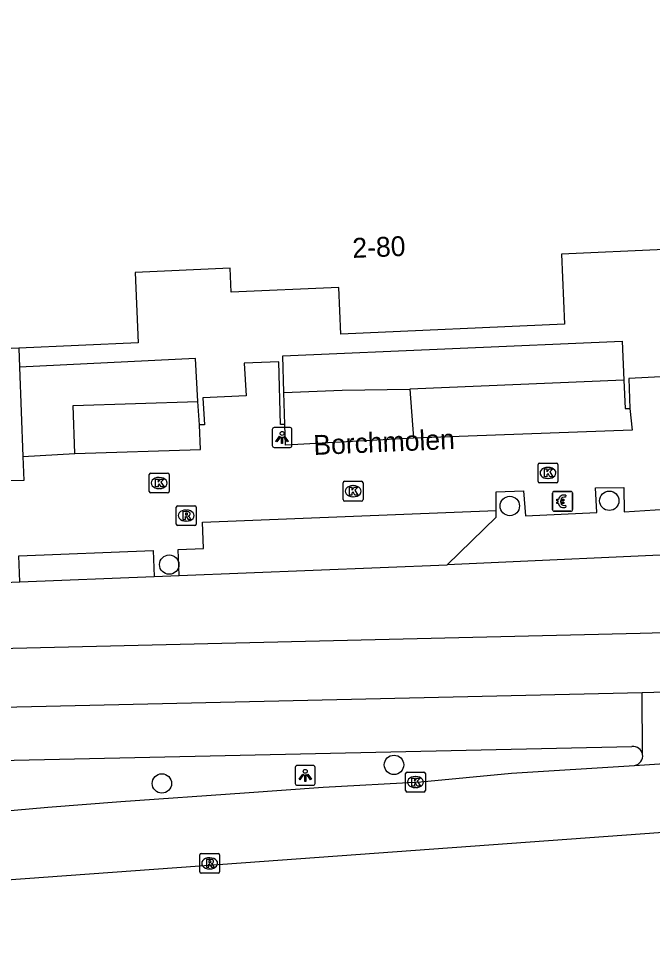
# Model space of a CAD drawing. Extents: x 161243 to 161752, y 384138 to 384885.
# Drawn here: x 161303.77 to 161335.74, y 384140.88 to 384187.42 of the extents above; entities that cross this region are included whole.
import ezdxf

# ---------------------------------------------------------------- set-up
doc = ezdxf.new("R2010")
doc.units = 0
for name, color, linetype in [('IMGEO_Betaalautomaat', 7, 'Continuous'), ('IMGEO_Boom', 7, 'Continuous'), ('IMGEO_Fietspad_gesloten', 7, 'Continuous'), ('IMGEO_Groenvoorziening', 7, 'Continuous'), ('IMGEO_Kolk', 7, 'Continuous'), ('IMGEO_Lichtpunt', 7, 'Continuous'), ('IMGEO_Openbare_ruimte_label', 7, 'Continuous'), ('IMGEO_Pand', 7, 'Continuous'), ('IMGEO_Pand_nummerreeks', 7, 'Continuous'), ('IMGEO_Parkeervlak_open', 7, 'Continuous'), ('IMGEO_Rijbaan_lokaal_gesloten', 7, 'Continuous'), ('IMGEO_Rijbaan_lokaal_open', 7, 'Continuous'), ('IMGEO_Rioolput', 7, 'Continuous'), ('IMGEO_Voetpad_open', 7, 'Continuous')]:
    doc.layers.add(name, color=color, linetype=linetype)

msp = doc.modelspace()

# ---------------------------------------------------------------- linework, layer by layer
at = {"layer": 'IMGEO_Betaalautomaat'}
for p, q in [((161330.699, 384162.651), (161330.699, 384163.492)), ((161330.699, 384163.492), (161330.699, 384162.651)), ((161330.774, 384163.575), (161331.615, 384163.575)), ((161331.615, 384163.575), (161330.774, 384163.575)), ((161331.698, 384163.501), (161331.698, 384162.66)), ((161331.698, 384162.66), (161331.698, 384163.501)), ((161330.982, 384163.039), (161330.982, 384163.107)), ((161331.103, 384163.107), (161331.103, 384163.039)), ((161331.361, 384163.38), (161331.344, 384163.28)), ((161331.624, 384162.576), (161330.783, 384162.576)), ((161330.783, 384162.576), (161331.624, 384162.576)), ((161331.348, 384162.874), (161331.37, 384162.787))]:
    msp.add_line(p, q, dxfattribs=at)
for points in [[(161330.982, 384163.107), (161330.913, 384163.107), (161330.913, 384163.176), (161330.992, 384163.176)], [(161330.987, 384162.97), (161330.913, 384162.97), (161330.913, 384163.039), (161330.982, 384163.039)], [(161331.114, 384163.176), (161331.261, 384163.176), (161331.261, 384163.107), (161331.103, 384163.107)], [(161331.103, 384163.039), (161331.261, 384163.039), (161331.261, 384162.97), (161331.117, 384162.97)]]:
    msp.add_lwpolyline(points, dxfattribs=at)
for centre, radius, start, end in [((161330.777, 384163.498), 0.0779, 92.4484, 184.2845), ((161330.777, 384163.498), 0.0779, 92.4484, 184.2845), ((161331.621, 384163.498), 0.0779, 2.4484, 94.2845), ((161331.621, 384163.498), 0.0779, 2.4484, 94.2845), ((161331.248, 384163.025), 0.267, 191.8096, 297.0389), ((161331.275, 384163.1), 0.293, 73.014, 165.0139), ((161331.281, 384163.113), 0.179, 69.3236, 159.5683), ((161331.281, 384163.04), 0.179, 202.7625, 291.8693), ((161330.777, 384162.654), 0.0779, 182.4484, 274.2845), ((161330.777, 384162.654), 0.0779, 182.4484, 274.2845), ((161331.621, 384162.654), 0.0779, 272.4484, 4.2845), ((161331.621, 384162.654), 0.0779, 272.4484, 4.2845)]:
    msp.add_arc(centre, radius, start, end, dxfattribs=at)
at = {"layer": 'IMGEO_Boom'}
for centre in [(161333.558, 384163.104), (161328.543, 384162.84), (161311.37, 384159.885), (161322.704, 384149.79), (161310.999, 384148.852)]:
    msp.add_circle(centre, 0.489, dxfattribs=at)
at = {"layer": 'IMGEO_Fietspad_gesloten'}
for points in [[(161335.217, 384153.424), (161294.886, 384152.501), (161264.254, 384151.917)], [(161262.525, 384149.114), (161334.701, 384150.711)]]:
    msp.add_lwpolyline(points, dxfattribs=at)
msp.add_arc((161334.763, 384150.231), 0.484, 9.9926, 97.3984, dxfattribs=at)
at = {"layer": 'IMGEO_Groenvoorziening'}
for points in [[(161317.154, 384168.56), (161317.096, 384170.413), (161334.208, 384171.151), (161334.294, 384169.18)], [(161312.811, 384168.108), (161312.699, 384170.282), (161303.821, 384169.831)], [(161334.294, 384169.18), (161323.501, 384168.735)], [(161334.294, 384169.18), (161334.357, 384167.748), (161334.6, 384167.762)], [(161352.045, 384161.086), (161325.389, 384159.875)]]:
    msp.add_lwpolyline(points, dxfattribs=at)
at = {"layer": 'IMGEO_Kolk'}
for p, q in [((161329.965, 384164.081), (161329.965, 384164.933)), ((161330.04, 384165.007), (161330.892, 384165.007)), ((161330.966, 384164.933), (161330.966, 384164.081)), ((161310.362, 384163.572), (161310.362, 384164.424)), ((161310.437, 384164.498), (161311.289, 384164.498)), ((161311.363, 384164.424), (161311.363, 384163.572)), ((161330.453, 384164.787), (161330.478, 384164.787)), ((161310.85, 384164.278), (161310.875, 384164.278)), ((161320.14, 384163.16), (161320.14, 384164.012)), ((161320.215, 384164.086), (161321.067, 384164.086)), ((161321.141, 384164.012), (161321.141, 384163.16)), ((161330.892, 384164.007), (161330.04, 384164.007)), ((161330.476, 384164.227), (161330.451, 384164.227)), ((161311.289, 384163.498), (161310.437, 384163.498)), ((161310.873, 384163.718), (161310.848, 384163.718)), ((161320.628, 384163.866), (161320.653, 384163.866)), ((161321.067, 384163.086), (161320.215, 384163.086)), ((161320.651, 384163.306), (161320.626, 384163.306)), ((161323.286, 384148.494), (161323.286, 384149.346)), ((161323.361, 384149.42), (161324.213, 384149.42)), ((161323.774, 384149.2), (161323.799, 384149.2)), ((161324.287, 384149.346), (161324.287, 384148.494)), ((161323.797, 384148.64), (161323.772, 384148.64)), ((161324.213, 384148.42), (161323.361, 384148.42))]:
    msp.add_line(p, q, dxfattribs=at)
for points in [[(161329.965, 384164.081), (161329.965, 384164.933)], [(161330.04, 384165.007), (161330.892, 384165.007)], [(161330.966, 384164.933), (161330.966, 384164.081)], [(161310.362, 384163.572), (161310.362, 384164.424)], [(161310.437, 384164.498), (161311.289, 384164.498)], [(161311.363, 384164.424), (161311.363, 384163.572)], [(161330.286, 384164.707), (161330.409, 384164.707), (161330.409, 384164.556), (161330.539, 384164.707), (161330.703, 384164.707), (161330.557, 384164.556), (161330.71, 384164.307), (161330.558, 384164.307), (161330.473, 384164.471), (161330.409, 384164.404), (161330.409, 384164.307), (161330.286, 384164.307), (161330.286, 384164.707)], [(161310.683, 384164.198), (161310.806, 384164.198), (161310.806, 384164.047), (161310.936, 384164.198), (161311.1, 384164.198), (161310.954, 384164.047), (161311.107, 384163.798), (161310.955, 384163.798), (161310.87, 384163.962), (161310.806, 384163.895), (161310.806, 384163.798), (161310.683, 384163.798), (161310.683, 384164.198)], [(161320.14, 384163.16), (161320.14, 384164.012)], [(161320.215, 384164.086), (161321.067, 384164.086)], [(161321.141, 384164.012), (161321.141, 384163.16)], [(161330.892, 384164.007), (161330.04, 384164.007)], [(161311.289, 384163.498), (161310.437, 384163.498)], [(161320.461, 384163.786), (161320.584, 384163.786), (161320.584, 384163.635), (161320.714, 384163.786), (161320.878, 384163.786), (161320.732, 384163.635), (161320.885, 384163.386), (161320.733, 384163.386), (161320.648, 384163.55), (161320.584, 384163.483), (161320.584, 384163.386), (161320.461, 384163.386), (161320.461, 384163.786)], [(161321.067, 384163.086), (161320.215, 384163.086)], [(161323.286, 384148.494), (161323.286, 384149.346)], [(161323.361, 384149.42), (161324.213, 384149.42)], [(161323.607, 384149.12), (161323.73, 384149.12), (161323.73, 384148.969), (161323.86, 384149.12), (161324.024, 384149.12), (161323.878, 384148.969), (161324.031, 384148.72), (161323.879, 384148.72), (161323.794, 384148.884), (161323.73, 384148.817), (161323.73, 384148.72), (161323.607, 384148.72), (161323.607, 384149.12)], [(161324.287, 384149.346), (161324.287, 384148.494)], [(161324.213, 384148.42), (161323.361, 384148.42)]]:
    msp.add_lwpolyline(points, dxfattribs=at)
for centre, start, end in [((161330.042, 384164.931), 91.552, 178.448), ((161330.042, 384164.931), 91.552, 178.448), ((161330.89, 384164.931), 1.552, 88.448), ((161330.89, 384164.931), 1.552, 88.448), ((161310.439, 384164.422), 91.552, 178.448), ((161310.439, 384164.422), 91.552, 178.448), ((161311.287, 384164.422), 1.552, 88.448), ((161311.287, 384164.422), 1.552, 88.448), ((161320.217, 384164.01), 91.552, 178.448), ((161320.217, 384164.01), 91.552, 178.448), ((161321.065, 384164.01), 1.552, 88.448), ((161321.065, 384164.01), 1.552, 88.448), ((161330.042, 384164.083), 181.552, 268.448), ((161330.042, 384164.083), 181.552, 268.448), ((161330.89, 384164.083), 271.552, 358.448), ((161330.89, 384164.083), 271.552, 358.448), ((161310.439, 384163.574), 181.552, 268.448), ((161310.439, 384163.574), 181.552, 268.448), ((161311.287, 384163.574), 271.552, 358.448), ((161311.287, 384163.574), 271.552, 358.448), ((161320.217, 384163.162), 181.552, 268.448), ((161320.217, 384163.162), 181.552, 268.448), ((161321.065, 384163.162), 271.552, 358.448), ((161321.065, 384163.162), 271.552, 358.448), ((161323.363, 384149.344), 91.552, 178.448), ((161323.363, 384149.344), 91.552, 178.448), ((161324.211, 384149.344), 1.552, 88.448), ((161324.211, 384149.344), 1.552, 88.448), ((161323.363, 384148.496), 181.552, 268.448), ((161323.363, 384148.496), 181.552, 268.448), ((161324.211, 384148.496), 271.552, 358.448), ((161324.211, 384148.496), 271.552, 358.448)]:
    msp.add_arc(centre, 0.0765, start, end, dxfattribs=at)
for centre, major_axis, ratio, start_param, end_param in [((161330.452, 384164.507), (-0.387, 0.002), 0.722429, 4.712389, 7.853982), ((161330.477, 384164.507), (-0.39, 0.002), 0.717154, 1.570796, 4.712389), ((161310.849, 384163.998), (-0.387, 0.002), 0.722429, 4.712389, 7.853982), ((161310.874, 384163.998), (-0.39, 0.002), 0.717154, 1.570796, 4.712389), ((161320.627, 384163.586), (-0.387, 0.002), 0.722429, 4.712389, 7.853982), ((161320.652, 384163.586), (-0.39, 0.002), 0.717154, 1.570796, 4.712389), ((161323.773, 384148.92), (-0.387, 0.002), 0.722429, 4.712389, 7.853982), ((161323.798, 384148.92), (-0.39, 0.002), 0.717154, 1.570796, 4.712389)]:
    msp.add_ellipse(centre, major_axis=major_axis, ratio=ratio, start_param=start_param, end_param=end_param, dxfattribs=at)
at = {"layer": 'IMGEO_Lichtpunt'}
for p, q in [((161316.562, 384166.698), (161316.562, 384165.891)), ((161316.562, 384166.698), (161316.562, 384165.891)), ((161317.464, 384166.793), (161316.656, 384166.793)), ((161317.464, 384166.793), (161316.656, 384166.793)), ((161317.558, 384165.891), (161317.558, 384166.698)), ((161317.558, 384165.891), (161317.558, 384166.698)), ((161316.656, 384165.797), (161317.464, 384165.797)), ((161316.656, 384165.797), (161317.464, 384165.797)), ((161317.726, 384149.664), (161317.726, 384148.857)), ((161317.726, 384149.664), (161317.726, 384148.857)), ((161318.628, 384149.759), (161317.82, 384149.759)), ((161318.628, 384149.759), (161317.82, 384149.759)), ((161318.722, 384148.857), (161318.722, 384149.664)), ((161318.722, 384148.857), (161318.722, 384149.664)), ((161317.82, 384148.763), (161318.628, 384148.763)), ((161317.82, 384148.763), (161318.628, 384148.763))]:
    msp.add_line(p, q, dxfattribs=at)
for points in [[(161316.936, 384166.362), (161316.975, 384166.334), (161316.787, 384166.072), (161316.749, 384166.099), (161316.936, 384166.362)], [(161317.038, 384166.314), (161317.085, 384166.314), (161317.085, 384165.992), (161317.038, 384165.992), (161317.038, 384166.314)], [(161317.148, 384166.334), (161317.186, 384166.361), (161317.373, 384166.099), (161317.334, 384166.071), (161317.148, 384166.334)], [(161318.1, 384149.328), (161318.139, 384149.3), (161317.951, 384149.038), (161317.913, 384149.065), (161318.1, 384149.328)], [(161318.202, 384149.28), (161318.249, 384149.28), (161318.249, 384148.958), (161318.202, 384148.958), (161318.202, 384149.28)], [(161318.312, 384149.3), (161318.35, 384149.327), (161318.537, 384149.065), (161318.498, 384149.037), (161318.312, 384149.3)]]:
    msp.add_lwpolyline(points, dxfattribs=at)
for centre in [(161317.061, 384166.496), (161318.225, 384149.462)]:
    msp.add_circle(centre, 0.0994, dxfattribs=at)
for centre, start, end in [((161316.656, 384166.698), 90, 180), ((161316.656, 384166.698), 90, 180), ((161317.464, 384166.698), 0, 90), ((161317.464, 384166.698), 0, 90), ((161316.656, 384165.891), 180, 270), ((161316.656, 384165.891), 180, 270), ((161317.464, 384165.891), 270, 0), ((161317.464, 384165.891), 270, 360), ((161317.82, 384149.664), 90, 180), ((161317.82, 384149.664), 90, 180), ((161318.628, 384149.664), 0, 90), ((161318.628, 384149.664), 0, 90), ((161317.82, 384148.857), 180, 270), ((161317.82, 384148.857), 180, 270), ((161318.628, 384148.857), 270, 0), ((161318.628, 384148.857), 270, 360)]:
    msp.add_arc(centre, 0.0946, start, end, dxfattribs=at)
at = {"layer": 'IMGEO_Pand'}
for points in [[(161354.21, 384187.419), (161352.267, 384187.333), (161352.85, 384174.043), (161347.371, 384173.803), (161347.422, 384172.637), (161341.583, 384172.381), (161341.478, 384174.793), (161336.389, 384174.569), (161336.336, 384175.763), (161331.14, 384175.535), (161331.295, 384172.004), (161320.023, 384171.509), (161319.92, 384173.854), (161314.498, 384173.616), (161314.445, 384174.825), (161309.65, 384174.615), (161309.805, 384171.068), (161303.785, 384170.804)], [(161303.785, 384170.804), (161301.481, 384170.703)]]:
    msp.add_lwpolyline(points, dxfattribs=at)
at = {"layer": 'IMGEO_Parkeervlak_open'}
for points in [[(161317.154, 384168.56), (161320.082, 384168.674), (161323.501, 384168.735)], [(161317.204, 384166.951), (161317.154, 384168.56)], [(161323.501, 384168.735), (161323.686, 384166.264)], [(161306.603, 384165.479), (161306.523, 384167.901), (161312.811, 384168.108)], [(161312.894, 384166.937), (161312.811, 384168.108)], [(161325.389, 384159.875), (161327.853, 384162.271), (161327.854, 384162.612)], [(161311.865, 384159.331), (161325.389, 384159.875)], [(161303.835, 384159.009), (161310.616, 384159.281)]]:
    msp.add_lwpolyline(points, dxfattribs=at)
at = {"layer": 'IMGEO_Rijbaan_lokaal_gesloten'}
for points in [[(161371.088, 384154.255), (161366.206, 384154.17), (161362.935, 384154.07), (161357.372, 384153.915), (161350.419, 384153.771), (161345.195, 384153.611), (161343.385, 384153.579), (161338.774, 384153.519), (161335.217, 384153.424)], [(161335.24, 384150.315), (161335.217, 384153.424)], [(161334.833, 384149.765), (161370.321, 384152.118), (161401.777, 384153.037)], [(161403.252, 384150.18), (161392.155, 384149.886), (161376.721, 384149.233), (161369.626, 384148.76), (161361.232, 384148.2), (161341.125, 384146.731), (161314.989, 384144.831), (161288.79, 384142.926), (161262, 384140.882)], [(161262.281, 384144.461), (161263.157, 384144.513), (161268.286, 384144.952), (161279.348, 384145.71), (161300.005, 384147.288), (161301.599, 384147.407), (161303.55, 384147.498), (161305.252, 384147.652), (161308.927, 384147.935), (161315.164, 384148.38), (161319.129, 384148.659), (161324.063, 384148.934), (161328.631, 384149.374), (161334.833, 384149.765)]]:
    msp.add_lwpolyline(points, dxfattribs=at)
msp.add_arc((161334.766, 384150.24), 0.48, 278.0133, 8.9838, dxfattribs=at)
at = {"layer": 'IMGEO_Rijbaan_lokaal_open'}
for points in [[(161338.722, 384167.982), (161338.543, 384167.984), (161338.427, 384170.967), (161336.765, 384170.952), (161336.811, 384169.377), (161334.54, 384169.266), (161334.6, 384167.762)], [(161317.204, 384166.951), (161316.974, 384166.944), (161316.892, 384170.116), (161315.15, 384170.049), (161315.246, 384168.401), (161313.064, 384168.294), (161313.149, 384166.936), (161312.894, 384166.937)], [(161334.6, 384167.762), (161334.711, 384166.67), (161323.686, 384166.264)], [(161303.985, 384165.331), (161304.04, 384164.132), (161301.787, 384164.071), (161301.734, 384165.047), (161292.771, 384164.738), (161292.597, 384166.742)], [(161306.603, 384165.479), (161312.938, 384165.688), (161312.894, 384166.937)], [(161323.686, 384166.264), (161317.237, 384165.9), (161317.204, 384166.951)], [(161303.985, 384165.331), (161306.603, 384165.479)], [(161327.854, 384162.612), (161327.856, 384163.556), (161329.226, 384163.603), (161329.34, 384162.352), (161332.935, 384162.507), (161332.87, 384163.751), (161334.297, 384163.777), (161334.305, 384162.547), (161337.426, 384162.754), (161351.957, 384163.332)], [(161311.865, 384159.331), (161311.812, 384160.649), (161313.096, 384160.7), (161313.043, 384162.017), (161327.854, 384162.612)], [(161303.835, 384159.009), (161303.782, 384160.326), (161310.563, 384160.598), (161310.616, 384159.281)], [(161310.616, 384159.281), (161311.865, 384159.331)], [(161302.621, 384158.96), (161303.835, 384159.009)]]:
    msp.add_lwpolyline(points, dxfattribs=at)
at = {"layer": 'IMGEO_Rioolput'}
for p, q in [((161311.726, 384161.93), (161311.726, 384162.782)), ((161311.801, 384162.856), (161312.653, 384162.856)), ((161312.214, 384162.636), (161312.239, 384162.636)), ((161312.727, 384162.782), (161312.727, 384161.93)), ((161312.237, 384162.076), (161312.212, 384162.076)), ((161312.653, 384161.856), (161311.801, 384161.856)), ((161312.981, 384145.324), (161313.833, 384145.324)), ((161312.906, 384144.398), (161312.906, 384145.25)), ((161313.394, 384145.104), (161313.419, 384145.104)), ((161313.907, 384145.25), (161313.907, 384144.398)), ((161313.833, 384144.324), (161312.981, 384144.324)), ((161313.417, 384144.544), (161313.392, 384144.544))]:
    msp.add_line(p, q, dxfattribs=at)
for points in [[(161311.726, 384161.93), (161311.726, 384162.782)], [(161311.801, 384162.856), (161312.653, 384162.856)], [(161312.315, 384162.554), (161312.063, 384162.556), (161312.063, 384162.156)], [(161312.241, 384162.475), (161312.187, 384162.475), (161312.187, 384162.394)], [(161312.727, 384162.782), (161312.727, 384161.93)], [(161312.063, 384162.156), (161312.187, 384162.156), (161312.187, 384162.318), (161312.198, 384162.318)], [(161312.187, 384162.394), (161312.239, 384162.394)], [(161312.245, 384162.289), (161312.316, 384162.156), (161312.456, 384162.156), (161312.391, 384162.282)], [(161312.653, 384161.856), (161311.801, 384161.856)], [(161312.981, 384145.324), (161313.833, 384145.324)], [(161312.906, 384144.398), (161312.906, 384145.25)], [(161313.495, 384145.022), (161313.243, 384145.024), (161313.243, 384144.624)], [(161313.243, 384144.624), (161313.367, 384144.624), (161313.367, 384144.786), (161313.378, 384144.786)], [(161313.421, 384144.943), (161313.367, 384144.943), (161313.367, 384144.862)], [(161313.367, 384144.862), (161313.419, 384144.862)], [(161313.907, 384145.25), (161313.907, 384144.398)], [(161313.833, 384144.324), (161312.981, 384144.324)], [(161313.425, 384144.757), (161313.496, 384144.624), (161313.636, 384144.624), (161313.571, 384144.75)]]:
    msp.add_lwpolyline(points, dxfattribs=at)
for centre, radius, start, end in [((161311.803, 384162.78), 0.0765, 91.552, 178.448), ((161311.803, 384162.78), 0.0765, 91.552, 178.448), ((161312.247, 384162.379), 0.0964, 77.0061, 93.1865), ((161312.261, 384162.436), 0.0378, 276.6634, 79.6772), ((161312.314, 384162.444), 0.109, 350.3612, 89.416), ((161312.651, 384162.78), 0.0765, 1.552, 88.448), ((161312.651, 384162.78), 0.0765, 1.552, 88.448), ((161312.197, 384162.265), 0.0533, 26.0293, 88.6989), ((161312.223, 384162.583), 0.19, 274.7715, 282.9687), ((161312.312, 384162.444), 0.112, 277.5842, 350.9817), ((161312.296, 384162.229), 0.108, 29.5134, 73.7905), ((161311.803, 384161.932), 0.0765, 181.552, 268.448), ((161311.803, 384161.932), 0.0765, 181.552, 268.448), ((161312.651, 384161.932), 0.0765, 271.552, 358.448), ((161312.651, 384161.932), 0.0765, 271.552, 358.448), ((161312.983, 384145.248), 0.0765, 91.552, 178.448), ((161312.983, 384145.248), 0.0765, 91.552, 178.448), ((161313.831, 384145.248), 0.0765, 1.552, 88.448), ((161313.831, 384145.248), 0.0765, 1.552, 88.448), ((161313.377, 384144.733), 0.0533, 26.0293, 88.6989), ((161313.403, 384145.051), 0.19, 274.7715, 282.9687), ((161313.427, 384144.847), 0.0964, 77.0061, 93.1865), ((161313.441, 384144.904), 0.0378, 276.6634, 79.6772), ((161313.494, 384144.912), 0.109, 350.3612, 89.416), ((161313.492, 384144.912), 0.112, 277.5842, 350.9817), ((161313.476, 384144.697), 0.108, 29.5134, 73.7905), ((161312.983, 384144.4), 0.0765, 181.552, 268.448), ((161312.983, 384144.4), 0.0765, 181.552, 268.448), ((161313.831, 384144.4), 0.0765, 271.552, 358.448), ((161313.831, 384144.4), 0.0765, 271.552, 358.448)]:
    msp.add_arc(centre, radius, start, end, dxfattribs=at)
for centre, major_axis, ratio, start_param, end_param in [((161312.213, 384162.356), (-0.387, 0.002), 0.722429, 4.712389, 7.853982), ((161312.238, 384162.356), (-0.39, 0.002), 0.717154, 1.570796, 4.712389), ((161313.393, 384144.824), (-0.387, 0.002), 0.722429, 4.712389, 7.853982), ((161313.418, 384144.824), (-0.39, 0.002), 0.717154, 1.570796, 4.712389)]:
    msp.add_ellipse(centre, major_axis=major_axis, ratio=ratio, start_param=start_param, end_param=end_param, dxfattribs=at)
at = {"layer": 'IMGEO_Voetpad_open'}
for points in [[(161303.785, 384170.804), (161303.821, 384169.831)], [(161303.821, 384169.831), (161303.985, 384165.331)], [(161302.754, 384155.653), (161335.122, 384156.432), (161352.209, 384156.901)]]:
    msp.add_lwpolyline(points, dxfattribs=at)

# ---------------------------------------------------------------- texts
at = {"layer": 'IMGEO_Openbare_ruimte_label'}
msp.add_text('Borchmolen', height=1, rotation=2.5219, dxfattribs=at).set_placement((161318.659, 384165.41))
at = {"layer": 'IMGEO_Pand_nummerreeks'}
msp.add_text('2-80', height=1, rotation=2.2976, dxfattribs=at).set_placement((161320.624, 384175.345))

doc.saveas('drawing.dxf')
